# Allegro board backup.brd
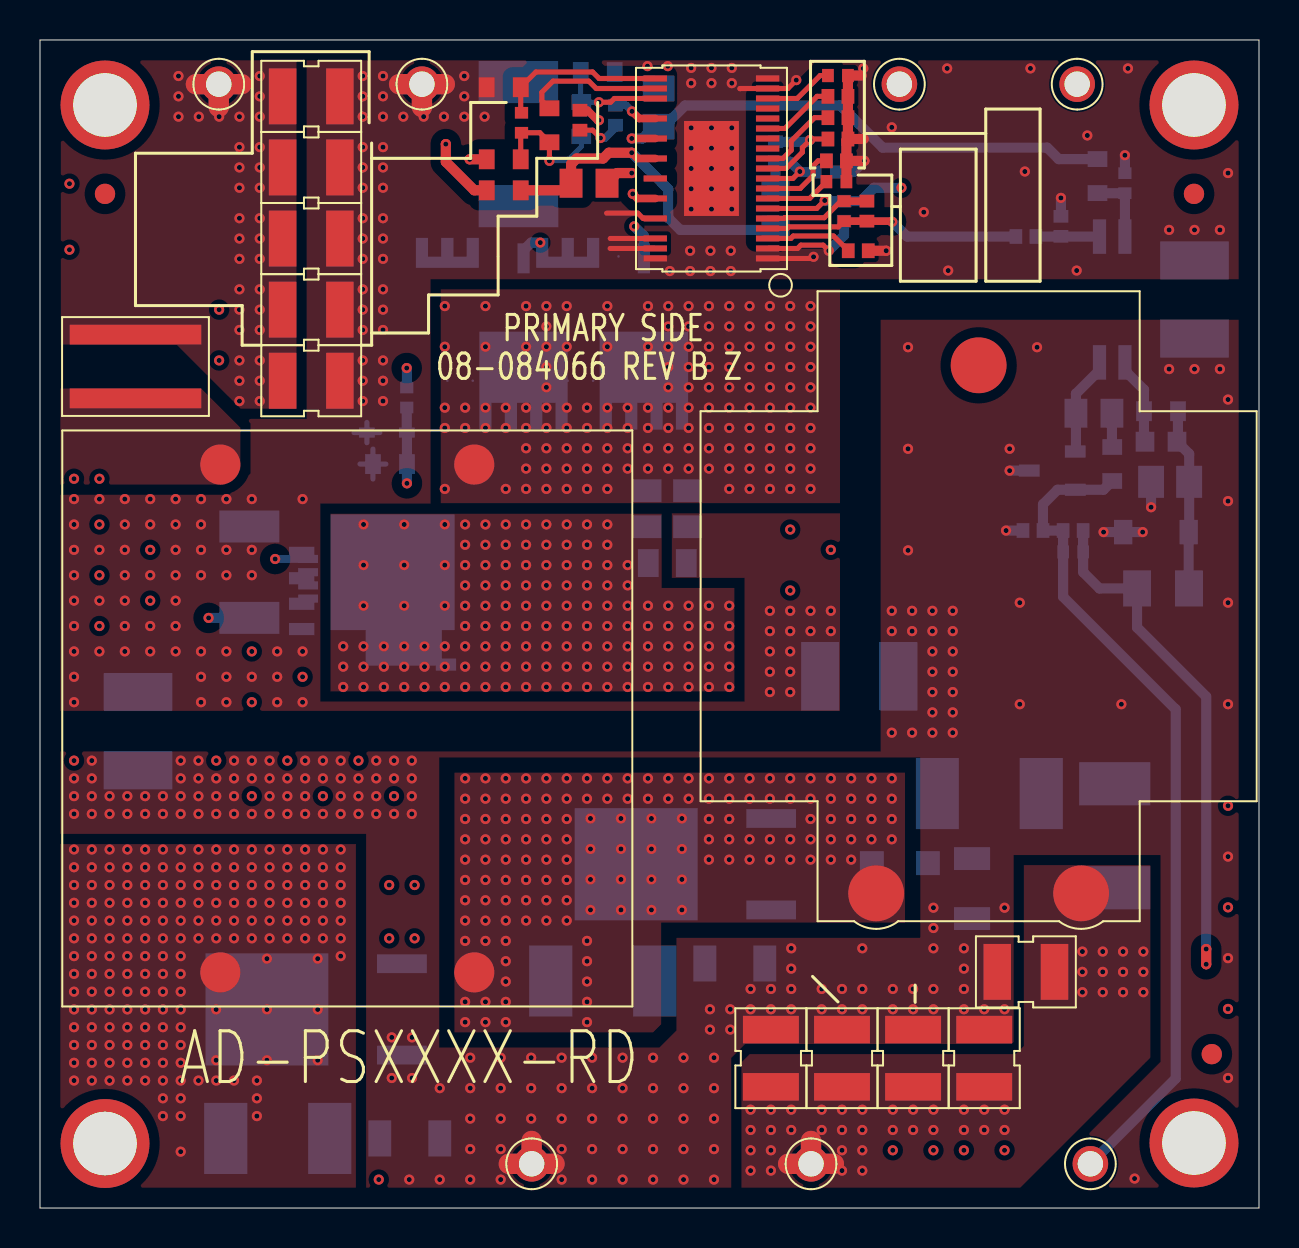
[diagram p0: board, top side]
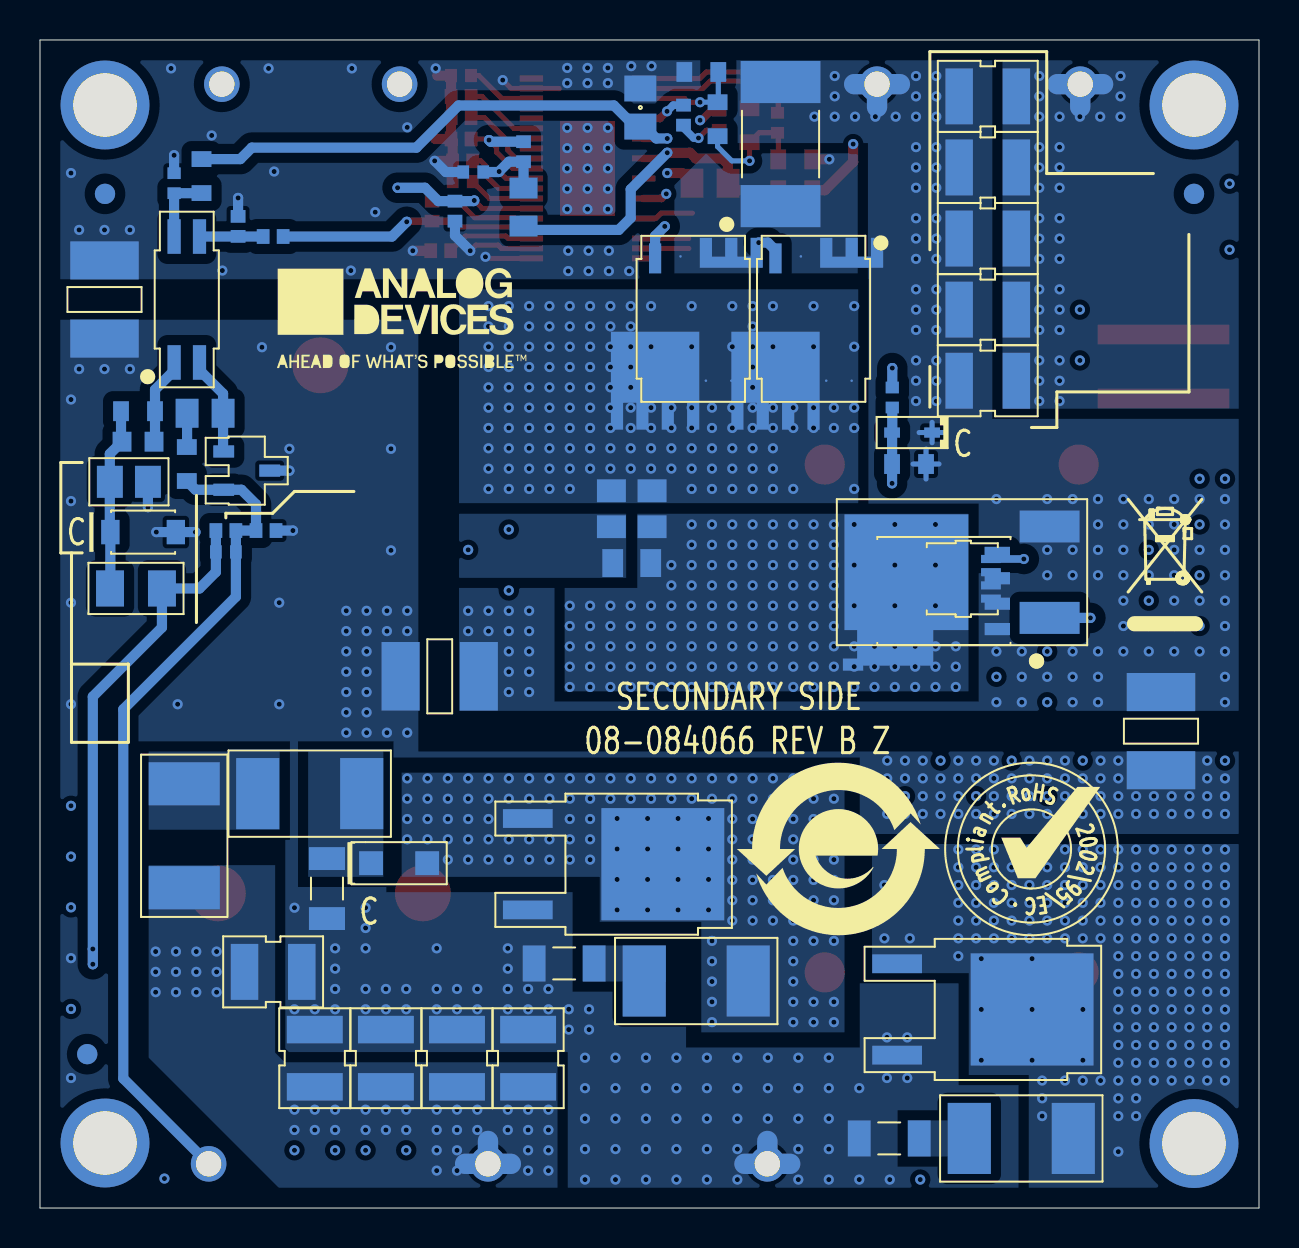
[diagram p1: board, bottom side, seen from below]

Outline 60.96 x 58.42 mm; copper layers: TOP, L2_GND, L3_SIG, L4_PWR, L5_PWR, L6_PWR, L7_GND, BOTTOM. Coordinates in mm from the lower left corner of the outline.
Outline path: 0,58.42 0,0 60.96,0 60.96,58.42 0,58.42

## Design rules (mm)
constraint set DEFAULT: min track width 0.203
net group _N100: nets _N100 _N250
net group _N372: nets _N372 N430
net group INTVCC: nets _N63 INTVCC
net group _N233: nets _N231 _N232 _N233 _N238
net group _N303: nets _N227 _N303 _N305
net group _N310: nets _N310
net group VIN: nets _N197 _N199 _N200
net group VO: nets _N54 _N55 _N59 _N61 VFB

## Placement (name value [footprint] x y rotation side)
C1  1UF  [C0805]  27.46 51.26 0 top
C2  1UF  [C0402]  39.29 51.82 180 bottom
C3  4.7UF  [C0805H60]  30.94 55.04 90 bottom
C4  1UF  [C0402]  39.83 51.33 0 top
C5  0.022uF  [C0402]  39.9 56.64 0 top
C6  470pF  [C0402]  40.21 49.86 270 top
C7  2.2UF  [C0402]  54.25 51.26 90 bottom
C8  4700pF  [C0603]  56.06 38.33 180 bottom
C9  2.2uF  [C0805H53]  56.52 36.32 180 bottom
C10  3900pF  [C0805]  52.7 39.75 0 bottom
C11  2200pF  [C0402]  24.08 54.28 90 top
C12  0.1UF  [C0402]  18.34 40.54 270 bottom
C13  1UF  [C0402]  51.66 32.82 180 bottom
C14  2200PF  [C1812H110]  40.97 26.59 0 bottom
C15  2200PF  [C1206]  46.61 15.98 270 bottom
C_D3SNUB  2200PF  [C1206]  18.49 3.48 0 bottom
C_D4SNUB  2200PF  [C1206]  34.75 12.23 0 bottom
CCLAMP  0.22UF  [C0805H55]  30.35 34.98 270 bottom
CIN1  10UF  [C1210H110]  13.56 55.6 0 top
CIN2  10UF  [C1210H110]  13.56 52.04 0 top
CIN3  10UF  [C1210H110]  13.56 48.49 0 top
CIN4  10UF  [C1210H110]  13.56 44.93 0 top
CIN5  10UF  [C1210H110]  13.56 41.38 0 top
CIN6  10UF  [C1210H110]  13.56 55.6 0 bottom
CIN7  10UF  [C1210H110]  13.56 52.04 0 bottom
CIN8  10UF  [C1210H110]  13.56 48.49 0 bottom
CIN9  10UF  [C1210H110]  13.56 44.93 0 bottom
CIN10  10UF  [C1210H110]  13.56 41.38 0 bottom
COUT1  10UF  [C1210H110]  36.55 7.49 90 top
COUT2  10UF  [C1210H110]  40.11 7.49 90 top
COUT3  10UF  [C1210H110]  43.66 7.49 90 top
COUT4  10UF  [C1210H110]  47.22 7.49 90 top
COUT5  10UF  [C1210H110]  49.3 11.81 180 top
COUT6  10UF  [C1210H110]  36.55 7.49 90 bottom
COUT7  10UF  [C1210H110]  40.11 7.49 90 bottom
COUT8  10UF  [C1210H110]  43.66 7.49 90 bottom
COUT9  10UF  [C1210H110]  47.22 7.49 90 bottom
COUT10  10UF  [C1210H110]  49.3 11.81 180 bottom
CSNUB  0.47UF  [C0805H55]  32.38 34.98 270 bottom
CY1  2200PF  [C1812H110]  4.9 23.85 270 bottom
CY2  2200PF  [C1812H110]  57.73 45.44 270 bottom
D1  BAS516,115  [SOD523F]  17.35 38.79 0 bottom
D2  CMMR1U-06 TR  [SOD123F]  43 17.25 180 bottom
D3  IDM08G120C5XTMA1  [PG-TO252-2]  12.9 9.93 270 bottom
D4  IDM08G120C5XTMA1  [PG-TO252-2]  31.37 17.2 270 bottom
D5  CMHZ4697 TR PBFREE  [SOD123FLH53]  55.8 33.81 180 bottom
L1  330UH/280UH  [LSML1075W1220H500]  46.94 30.1 0 top
NOREF  -  [unnamed]  3.25 50.72 0 top
NOREF#2  -  [#2]  0 58.42 0 top
NOREF#3  -  [#2]  105.61 60.12 0 top
NOREF#4  -  [#2]  210.86 -85.93 180 top
NOREF#5  -  [#2]  38.05 1.19 0 top
NOREF#6  -  [#2]  197.52 -89.49 0 top
NOREF#7  -  [#2]  60.96 0 90 top
NOREF#8  -  [unnamed]  57.71 3.25 0 top
NOREF#9  -  [unnamed]  3.25 55.17 0 top
NOREF#10  -  [unnamed]  57.71 50.72 0 top
NOREF#11  -  [#2]  172.74 -85.93 0 top
NOREF#12  -  [unnamed]  3.25 3.23 0 top
NOREF#13  -  [unnamed]  57.71 55.17 0 top
NOREF#14  -  [#2]  197.59 -85.93 0 top
NOREF#15  -  [#2]  214.42 -102.46 0 top
NOREF#16  -  [#2]  218.79 -87.41 0 top
NOREF#17  -  [#2]  186.04 -99.65 0 top
NOREF#18  -  [#2]  214.42 -59.45 0 top
NOREF#19  -  [#2]  -331.47 -377.44 0 top
NOREF#20  -  [#2]  60.96 0 90 top
NOREF#21  -  [#2]  31.19 73.33 0 top
NOREF#22  -  [#2]  166.3 -89.49 0 top
NOREF#23  -  [#2]  9.09 35.74 0 top
NOREF#24  -  [#2]  1.65 1.68 0 top
NOREF#25  -  [#2]  0 58.42 270 top
NOREF#26  -  [#2]  151.22 -106.76 0 top
NOREF#27  -  [#2]  60.96 58.42 180 top
NOREF#28  -  [#2]  98.15 45.06 0 top
NOREF#29  -  [#2]  208.32 -63.71 0 top
NOREF#30  -  [unnamed]  58.6 7.7 180 top
NOREF#31  -  [#2]  172.71 -45.29 0 top
NOREF#32  -  [#2]  -331.47 -377.44 0 top
NOREF#33  -  [#2]  -331.47 -377.44 0 top
NOREF#34  -  [#2]  0 0 0 top
NOREF#35  -  [unnamed]  58.6 7.7 180 bottom
NOREF#36  -  [#2]  4.9 28.91 180 bottom
NOREF#37  -  [#2]  21.03 17.96 180 bottom
NOREF#38  -  [unnamed]  57.71 50.72 180 bottom
NOREF#39  -  [unnamed]  3.25 50.72 180 bottom
NOREF#40  -  [#2]  11.38 17.96 180 bottom
NOREF#41  -  [#2]  43.16 44.48 180 bottom
Q1  IAUCN10S7N021ATMA1  [PG-TDSON-8_B]  28.3 44.48 0 bottom
Q2  IAUCN10S7N021ATMA1  [PG-TDSON-8_B]  22.28 44.48 0 bottom
Q4  DMP10H400SK3-13  [DPAK]  15.19 31.8 90 bottom
Q5  SISS71DN-T1-GE3  [POWERPAK1212-8_SP]  14.84 31.47 90 bottom
Q6  SIR873DP-T1-GE3  [POWERPAKSO8]  15.75 30.86 90 bottom
R1  0  [R0603]  23.19 50.9 0 top
R2  100K  [R0805]  36.78 50.06 90 bottom
R3  14.7K  [R0402]  36.78 52.83 270 bottom
R4  2.55K  [R0402]  39.9 53.47 180 top
R5  249K  [R0402]  39.83 52.37 180 top
R6  44.2K  [R0402]  39.9 54.53 180 top
R7  100K  [R0402]  39.9 55.6 180 top
R8  52.3K  [R0402]  41.35 49.86 270 top
R9  59K  [R0402]  49.3 48.59 0 bottom
R10  340  [R0402]  51.05 49.1 90 bottom
R11  100  [R0603]  52.88 51.61 270 bottom
R12  1.5K  [R0603]  56.06 39.85 180 bottom
R13  10K  [R1206-2]  56.16 30.99 0 bottom
R14  56.2K  [R0603]  53.62 37.21 270 bottom
R15  3.01K  [R0603]  25.48 54.15 270 top
R16  100  [R0603]  23.19 52.45 180 top
R17  100  [R0603]  23.19 56.06 180 top
R18  0  [R0603]  27.08 54.46 270 bottom
R19  0  [R0603]  27.89 56.82 0 bottom
R20  10K  [R0603]  17.5 37.21 180 bottom
R21  124K  [R2512H31]  47.47 20.73 0 bottom
R22  124K  [R2512H31]  53.75 18.62 90 bottom
R23  0  [R0402]  28.78 54.66 270 bottom
R24  10K  [R0402]  27 54.41 270 top
R_D3SNUB  124K  [R2512H31]  11.89 3.48 0 bottom
R_D4SNUB  124K  [R2512H31]  28.14 11.35 0 bottom
RC  31042-00-21-00-00-08-0  [MILLMAX3102]  42.98 56.21 0 top
RFB1  196K  [R0402]  51.66 33.88 180 bottom
RFB2  9.53K  [R0402]  49.66 33.88 180 bottom
RJUMPER  0  [R1225H28]  4.78 42.09 270 top
RSNS  0.02  [R2512H35]  23.93 53.21 90 bottom
RSNUB  200  [R0805]  31.37 32.26 180 bottom
RSYNC  2K  [R0402]  40.21 49.86 270 bottom
RT  82.5K  [R0402]  40.92 47.88 0 top
SYNC  31042-00-21-00-00-08-0  [MILLMAX3102]  51.87 56.21 0 top
T1  P26R2-0322-18R0  [TSML1102W1114H610]  15.37 24.49 180 top
TRIM  31042-00-21-00-00-08-0  [MILLMAX3102]  52.53 2.21 0 top
U1  LT3753EFE#PBF  [TSSOP38_31P_PAD4_75X2_74_05-08-1865]  33.58 51.99 90 top
U2  AN431AN-ATRG1  [SOT23_B]  50.62 36.88 270 bottom
U3  PS2801C-1-P-A  [SSOP4]  53.62 45.44 180 bottom
UNK+VIN  31042-00-21-00-00-08-0  [MILLMAX3102]  8.94 56.21 0 top
UNK+VOUT  31042-00-21-00-00-08-0  [MILLMAX3102]  38.56 2.21 0 top
UNK-VIN  31042-00-21-00-00-08-0  [MILLMAX3102]  19.1 56.21 0 top
UNK-VOUT  31042-00-21-00-00-08-0  [MILLMAX3102]  24.59 2.21 0 top

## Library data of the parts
C1 = CAP: User Part Number: UPN; Tolerance: 10; alternate symbols: (C0805); tolerance: 10
C2 C4-C7 C11-C13 = CAP: User Part Number: UPN; Tolerance: 10; alternate symbols: (C0402); tolerance: 10
C3 = CAP: Tolerance: 10; User Part Number: UPN; alternate symbols: (C0805H60); tolerance: 10
C8 = CAP: User Part Number: UPN; Tolerance: 5; alternate symbols: (C0603); tolerance: 5
C9 = CAP: Tolerance: 10; User Part Number: UPN; alternate symbols: (C0805H53); tolerance: 10
C10 = CAP: User Part Number: UPN; Tolerance: 5; alternate symbols: (C0805); tolerance: 5
C14 CY1 CY2 = CAP: Tolerance: 10; User Part Number: UPN; alternate symbols: (C1812H110); tolerance: 10
C15 C_D3SNUB C_D4SNUB = CAP: User Part Number: UPN; Tolerance: 5; alternate symbols: (C1206); tolerance: 5
CCLAMP CSNUB = CAP: User Part Number: UPN; Tolerance: 10; alternate symbols: (C0805H55); tolerance: 10
CIN1-CIN10 COUT1-COUT10 = CAP: Tolerance: 20; User Part Number: UPN; alternate symbols: (C1210H110); tolerance: 20
D1 = DIO: Tolerance: N/A; User Part Number: UPN; alternate symbols: (SOD523F); tolerance: N/A
D2 = DIO: Tolerance: N/A; User Part Number: UPN; alternate symbols: (SOD123F); tolerance: N/A
D3 D4 = DIOSCHOTTKY3P_V15: User Part Number: UPN; Tolerance: N/A; alternate symbols: (PG-TO252-2); tolerance: N/A
D5 = DIOZNR: User Part Number: UPN; Tolerance: 5; alternate symbols: (SOD123FLH53); tolerance: 5
L1 = CHOKE3P_V3: User Part Number: UPN; Tolerance: N/A; alternate symbols: (LSML1075W1220H500); tolerance: N/A
Q1 Q2 = TRANNMOSFET8P: Tolerance: N/A; User Part Number: UPN; alternate symbols: (PG-TDSON-8_B); tolerance: N/A
Q4 = TRANPMOSFET_V11: Tolerance: N/A; User Part Number: UPN; alternate symbols: (DPAK); tolerance: N/A
Q5 = TRANPMOSFET_V9: Tolerance: N/A; User Part Number: UPN; alternate symbols: (POWERPAK1212-8_SP); tolerance: N/A
Q6 = TRANPMOSFET_V9: Tolerance: N/A; User Part Number: UPN; alternate symbols: (POWERPAKSO8); tolerance: N/A
R1 R18 R19 = RES: User Part Number: UPN; Tolerance: JUMPER; alternate symbols: (R0603); tolerance: JUMPER
R2 = RES: User Part Number: UPN; Tolerance: 1; alternate symbols: (R0805); tolerance: 1
R3-R9 R24 RFB1 RFB2 RSYNC RT = RES: User Part Number: UPN; Tolerance: 1; alternate symbols: (R0402); tolerance: 1
R10 = RES: User Part Number: UPN; Tolerance: 0.1; alternate symbols: (R0402); tolerance: 0.1
R11 R14-R17 R20 = RES: User Part Number: UPN; Tolerance: 1; alternate symbols: (R0603); tolerance: 1
R12 = RES: User Part Number: UPN; Tolerance: 5; alternate symbols: (R0603); tolerance: 5
R13 = RES: Tolerance: 5; User Part Number: UPN; alternate symbols: (R1206-2); tolerance: 5
R21 R22 R_D3SNUB R_D4SNUB = RES: User Part Number: UPN; Tolerance: 1; alternate symbols: (R2512H31); tolerance: 1
R23 = RES: User Part Number: UPN; Tolerance: JUMPER; alternate symbols: (R0402); tolerance: JUMPER
RC SYNC TRIM UNK+VIN UNK+VOUT UNK-VIN UNK-VOUT = CNTP1P: User Part Number: UPN; Tolerance: N/A; alternate symbols: (MILLMAX3102); tolerance: N/A
RJUMPER = RES: User Part Number: UPN; Tolerance: N/A; alternate symbols: (R1225H28); tolerance: N/A
RSNS = RES: User Part Number: UPN; Tolerance: 1; alternate symbols: (R2512H35); tolerance: 1
RSNUB = RES: User Part Number: UPN; Tolerance: 5; alternate symbols: (R0805); tolerance: 5
T1 = XFMR_4P_V7: User Part Number: UPN; Tolerance: N/A; alternate symbols: (TSML1102W1114H610); tolerance: N/A
U1 = ADLT3753: Tolerance: N/A; User Part Number: UPN; alternate symbols: (TSSOP38_31P_PAD4_75X2_74_05-08-1865); tolerance: N/A
U2 = ICAN431: User Part Number: UPN; Tolerance: N/A; alternate symbols: (SOT23_B); tolerance: N/A
U3 = TRANPS2801_1: User Part Number: UPN; Tolerance: N/A; alternate symbols: (SSOP4); tolerance: N/A

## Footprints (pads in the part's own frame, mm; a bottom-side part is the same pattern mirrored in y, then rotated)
C0402
  rect 0.584x0.66 smd: 1(-0.5,0) 2(0.5,0)
C0603
  rect 0.94x0.991 smd: 1(-0.8,0) 2(0.8,0)
C0805
  rect 1.143x1.448 smd: 1(-0.9,0) 2(0.9,0)
C0805H53
  rect 1.295x1.6 smd: 1(-0.953,0) 2(0.953,0)
C0805H55
  rect 1.143x1.448 smd: 1(-0.9,0) 2(0.9,0)
C0805H60
  rect 1.295x1.6 smd: 1(-0.953,0) 2(0.953,0)
C1206
  rect 1.143x1.803 smd: 1(-1.5,0) 2(1.5,0)
C1210H110
  rect 1.372x2.794 smd: 1(-1.431,0) 2(1.431,0)
C1812H110
  rect 1.905x3.429 smd: 1(-1.956,0) 2(1.956,0)
DPAK
  rect 1.6x2.997 smd: 1(-2.286,-4.718) 3(2.286,-4.718)
  rect 5.791x6.198 smd: 4(0,2.445)
LSML1075W1220H500
  round 2.794 smd: 1(-5.125,-14.36) 2(5.125,-14.36) 3(0,12.05)
MILLMAX3102
  round 1.778 hole 1.27: 1(0,0)
PG-TDSON-8_B
  custom 0.375x0.375 smd: 1(-1.905,-3.3)
  round 0.127 smd: 2(-0.635,-3.12) 3(0.635,-3.12) 6(0.635,3.097) 7(-0.635,3.097) 8(-1.905,3.097)
  rect 0.61x1.499 smd: 4(1.905,-3.021)
  custom 1.105x1.105 smd: 5(1.905,3.097)
PG-TO252-2
  rect 0.94x2.489 smd: 1(-2.285,-5.195) 2(2.285,-5.195)
  rect 5.613x6.147 smd: 3(0,1.555)
POWERPAK1212-8_SP
  rect 0.406x0.991 smd: 1(-0.991,-1.435) 2(-0.33,-1.435) 3(0.33,-1.435) 4(0.991,-1.435)
  round 0.127 smd: 5(0.991,1.676) 6(0.33,1.676) 7(-0.33,1.676)
  custom 0.559x0.559 smd: 8(-0.991,1.676)
POWERPAKSO8
  rect 0.61x1.27 smd: 1(-1.905,-2.667) 2(-0.635,-2.667) 3(0.635,-2.667) 4(1.905,-2.667)
  rect 0.61x1.016 smd: 5(1.905,2.794) 6(0.635,2.794) 7(-0.635,2.794)
  custom 1.041x1.041 smd: 8(-1.905,2.794)
R0402
  rect 0.635x0.737 smd: 1(-0.5,0) 2(0.5,0)
R0603
  rect 0.787x0.991 smd: 1(-0.85,0) 2(0.85,0)
R0805
  rect 1.041x1.397 smd: 1(-0.95,0) 2(0.95,0)
R1206-2
  rect 1.397x1.803 smd: 1(-1.298,0) 2(1.298,0)
R1225H28
  rect 0.991x6.579 smd: 1(-1.595,0) 2(1.595,0)
R2512H31
  rect 2.159x3.556 smd: 1(-2.6,0) 2(2.6,0)
R2512H35
  rect 2.108x3.988 smd: 1(-3.104,0) 2(3.104,0)
SOD123F
  rect 1.194x1.194 smd: A(1.403,0) C(-1.403,0)
SOD123FLH53
  rect 0.914x1.219 smd: A(1.638,0) C(-1.638,0)
SOD523F
  rect 0.787x0.508 smd: A(1,0) C(-1,0)
SOT23_B
  rect 0.61x1.041 smd: 1(-0.958,-1.15) 2(0.958,-1.15) 3(0,1.15)
SSOP4
  rect 0.66x1.727 smd: 1(-0.635,-3.149) 2(0.635,-3.149) 3(0.635,3.149) 4(-0.635,3.149)
TSML1102W1114H610
  round 2.007 smd: 2(-6.35,-12.7) 6(6.35,-12.7) 9(6.35,12.7) 13(-6.35,12.7)
TSSOP38_31P_PAD4_75X2_74_05-08-1865
  rect 0.305x1.168 smd: 1(-4.5,-2.809) 2(-4,-2.809) 3(-3.5,-2.809) 4(-3,-2.809) 5(-2.5,-2.809) 6(-2,-2.809) 7(-1.5,-2.809) 8(-1,-2.809) 9(-0.5,-2.809) 10(0,-2.809) 11(0.5,-2.809) 12(1,-2.809) 13(1.5,-2.809) 14(2,-2.809) 15(2.5,-2.809) 16(3,-2.809) 17(3.5,-2.809) 18(4,-2.809) 19(4.5,-2.809) 20(4.5,2.809) 21(4,2.809) 22(3.5,2.809) 24(2.5,2.809) 26(1.5,2.809) 28(0.5,2.809) 30(-0.5,2.809) 32(-1.5,2.809) 34(-2.5,2.809) 36(-3.5,2.809) 37(-4,2.809) 38(-4.5,2.809)
  rect 4.75x2.743 smd: 39(0,0)
unnamed
  round 1.016 smd: (0,0)

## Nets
AGND: C1.2(N2) C2.1 C3.2(N2) C4.2(N2) C5.2(N2) C7.2(N2) C14.1 CIN1.2(N2) CIN2.2(N2) CIN3.2(N2) CIN4.2(N2) CIN5.2(N2) CIN6.2(N2) CIN7.2(N2) CIN8.2(N2) CIN9.2(N2) CIN10.2(N2) CY1.1 CY2.1 D1.C Q4.3(S) Q5.1 Q5.2 Q5.3(S3) Q6.1 Q6.2 Q6.3(S3) R4.1 R5.1 R6.1 R7.1 R10.2(N2) R17.2(N2) R19.2(N2) R20.2(N2) R24.1 RSNS.2(N2) RSYNC.2(N2) RT.2(N2) U1.1 U1.2 U1.18 U1.19 U1.34 U1.36 U1.37 U1.38 U1.39 UNK-VIN.1
GND_ISO: C9.2(N2) C14.2(N2) C15.2(N2) C_D3SNUB.2(N2) C_D4SNUB.2(N2) COUT1.2(N2) COUT2.2(N2) COUT3.2(N2) COUT4.2(N2) COUT5.2(N2) COUT6.2(N2) COUT7.2(N2) COUT8.2(N2) COUT9.2(N2) COUT10.2(N2) CY1.2(N2) CY2.2(N2) D3.2 D4.2 D5.A(P) RFB2.2(N2) U2.3 UNK-VOUT.1
VIN: CIN1.1 CIN2.1 CIN3.1 CIN4.1 CIN5.1 CIN6.1 CIN7.1 CIN8.1 CIN9.1 CIN10.1 R1.1 RJUMPER.1 UNK+VIN.1
VIN_X: RJUMPER.2(N2) T1.6
_N37: D3.1 D3.3(CASE) R_D3SNUB.1 T1.9
_N54: C10.2(N2) R14.1
_N55: C10.1 U2.1 U3.2
_N59: C8.1 C9.1 D5.C R12.1 R13.2(N2)
_N61: C8.2(N2) R12.2(N2) U3.1
_N63: C7.1 R11.2(N2) U3.4
_N100: C12.1 U1.32
_N197: C1.1 R1.2(N2) R2.1 U1.28(VIN)
_N199: R3.1 R4.2(N2) U1.10
_N200: C2.2(N2) R2.2(N2) R3.2(N2) RC.1(N1) U1.9
_N202: R5.2(N2) U1.8
_N203: R6.2(N2) U1.11
_N204: R7.2(N2) U1.14
_N213: RT.1 U1.3
_N216: C4.1 U1.7
_N217: C5.1 U1.17
_N227: C6.1 R8.1 U1.5
_N231: R18.1 R19.1 U1.22
_N232: C11.1 R15.2(N2) R16.1 R18.2(N2)
_N233: R15.1 U1.21
_N238: C11.2(N2) R17.1 U1.20
_N250: C12.2(N2) D1.A(P) Q4.1 Q5.4 Q6.4 R20.1
_N264: R21.2(N2) R22.2(N2)
_N265: C15.1 D2.C R21.1
_N274: D2.A(P) D4.1 D4.3(CASE) L1.1 R_D4SNUB.1 T1.13(N4)
_N303: C6.2(N2) R8.2(N2) R9.1 U1.4
_N305: R9.2(N2) R10.1 U3.3(EMITTER)
_N310: CSNUB.2(N2) RSNUB.1
_N365: CCLAMP.2(N2) Q4.4 Q5.5 Q5.6 Q5.7 Q5.8 Q6.5 Q6.6 Q6.7 Q6.8 RSNUB.2(N2)
_N372: R23.1 U1.24
_N375: C_D4SNUB.1 R_D4SNUB.2(N2)
_N387: C_D3SNUB.1 R_D3SNUB.2(N2)
INTVCC: C3.1 R11.1 U1.26
N396: CCLAMP.1 CSNUB.1 Q1.5 Q1.6 Q1.7 Q1.8 Q2.5 Q2.6 Q2.7 Q2.8 T1.2
N430: Q1.4 Q2.4 R23.2(N2) R24.2(N2)
N436: Q1.1 Q1.2 Q1.3(S3) Q2.1 Q2.2 Q2.3(S3) R16.2(N2) RSNS.1
SYNC: RSYNC.1 SYNC.1(N1) U1.6
VFB: C13.2(N2) R14.2(N2) RFB1.2(N2) RFB2.1 TRIM.1(N1) U2.2(REF)
VO: C13.1 COUT1.1 COUT2.1 COUT3.1 COUT4.1 COUT5.1 COUT6.1 COUT7.1 COUT8.1 COUT9.1 COUT10.1 L1.2 R13.1 R22.1 RFB1.1 UNK+VOUT.1

Pads without a net: L1 3; U1 12 13 15 16 30

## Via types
v1: diameter 0.508, hole 0.254, TOP to BOTTOM, 1065 vias

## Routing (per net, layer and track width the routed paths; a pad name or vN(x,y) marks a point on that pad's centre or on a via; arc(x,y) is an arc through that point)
AGND: length 66.7
  TOP w0.254: U1.34 30.16,49.49 29.9,49.76 28.34,49.76 ; v1(38.68,47.57) 38.6,47.49 U1.1 ; v1(39.45,47.88) 39.17,48.16 38.05,48.16 37.88,47.99 U1.2 ; U1.36 28.52,48.49 ; v1(37.82,56.41) 37.4,55.99 U1.18 35.01,55.99 35,55.98 ; U1.37 28.51,47.99
  TOP w0.381: R24.1 27.38,54.91 27.88,54.41 v1(27.95,54.41)
  TOP w0.508: C1.2 28.87,51.77 v1(29.59,51.77) ; 41.1,56.64 C5.2 R7.1 R6.1 R4.1 ; R4.1 41.2,53.47 ; R4.1 40.33,53.39 R5.1 ; R5.1 C4.2 ; R5.1 v1(41.22,52.37) ; RT.2 v1(42.32,47.88)
  TOP w1.016: 17.96,56.21 UNK-VIN.1 ; UNK-VIN.1 19.1,55.07 ; UNK-VIN.1 20.24,56.21
  L2_GND w1.016: 19.1,55.07 UNK-VIN.1 ; UNK-VIN.1 20.24,56.21 ; UNK-VIN.1 17.96,56.21
  L3_SIG w0.203: v1(16.14,53.06) v1(16.14,52.04) ; v1(17.15,53.06) v1(17.15,52.04)
  L3_SIG w1.016: 19.1,55.07 UNK-VIN.1 ; UNK-VIN.1 17.96,56.21 ; UNK-VIN.1 20.24,56.21
  L4_PWR w1.016: UNK-VIN.1 20.24,56.21 ; UNK-VIN.1 17.96,56.21 ; UNK-VIN.1 19.1,55.07
  L5_PWR w1.016: UNK-VIN.1 20.24,56.21 ; UNK-VIN.1 19.1,55.07 ; UNK-VIN.1 17.96,56.21
  L6_PWR w1.016: UNK-VIN.1 20.24,56.21 ; UNK-VIN.1 17.96,56.21 ; UNK-VIN.1 19.1,55.07
  L7_GND w1.016: UNK-VIN.1 20.24,56.21 ; UNK-VIN.1 19.1,55.07 ; UNK-VIN.1 17.96,56.21
  BOTTOM w0.254: D1.C 17,38.79 ; D1.C 16.35,38.28 ; D1.C 16.35,39.29 ; D1.C 15.7,38.79 ; 16.65,36.46 R20.2 ; R20.2 16.65,37.96 ; R20.2 17.3,37.21 ; R20.2 16,37.21
  BOTTOM w0.508: v1(39.45,47.88) 40.21,48.64 RSYNC.2 ; v1(41.22,52.37) 40.67,51.82 C2.1 ; R10.2 v1(51.05,50.52) ; C7.2 v1(54.25,52.65)
  BOTTOM w1.016: UNK-VIN.1 20.24,56.21 ; UNK-VIN.1 19.1,55.07 ; UNK-VIN.1 17.96,56.21
  vias: v1(1.47,51.23) v1(1.47,47.93) v1(1.7,35.46) v1(1.7,34.19) v1(1.7,32.92) v1(1.7,31.65) v1(1.7,30.38) v1(1.7,29.11) v1(1.7,27.84) v1(1.7,26.57) v1(1.7,25.3) v1(2.97,35.46) v1(2.97,32.92) v1(2.97,30.38) v1(2.97,27.84) v1(4.24,35.46) v1(4.24,34.19) v1(4.24,32.92) v1(4.24,31.65) v1(4.24,30.38) v1(4.24,29.11) v1(4.24,27.84) v1(5.51,35.46) v1(5.51,34.19) v1(5.51,31.65) v1(5.51,29.11) v1(5.51,27.84) v1(6.78,35.46) v1(6.78,34.19) v1(6.78,32.92) v1(6.78,31.65) v1(6.78,30.38) v1(6.78,29.11) v1(6.78,27.84) v1(8.05,35.46) v1(8.05,34.19) v1(8.05,32.92) v1(8.05,31.65) v1(8.05,27.84) v1(8.05,26.57) v1(8.05,25.3) v1(9.32,35.46) v1(9.32,32.92) v1(9.32,31.65) v1(9.32,27.84) v1(9.32,26.57) v1(9.32,25.3) v1(10.59,35.46) v1(10.59,32.92) v1(10.59,31.65) v1(10.59,26.57) v1(11.86,27.84) v1(11.86,26.57) v1(11.86,25.3) v1(13.13,35.46) v1(13.13,27.84) v1(13.13,25.3) v1(16.14,56.62) v1(16.14,55.6) v1(16.14,54.58) v1(16.14,51.03) v1(16.14,49.5) v1(16.14,48.49) v1(16.14,47.47) v1(16.14,45.95) v1(16.14,44.93) v1(16.14,43.92) v1(16.14,42.39) v1(16.14,41.38) v1(16.14,40.36) v1(17.15,56.62) v1(17.15,55.6) v1(17.15,54.58) v1(17.15,51.03) v1(17.15,49.5) v1(17.15,48.49) v1(17.15,47.47) v1(17.15,45.95) v1(17.15,44.93) v1(17.15,43.92) v1(17.15,42.39) v1(17.15,41.38) v1(17.15,40.36) v1(18.17,54.58) v1(19.19,54.58) v1(20.2,54.58) v1(21.22,56.62) v1(21.22,55.6) v1(21.22,54.58) v1(22.23,54.58) v1(30.38,57.11) v1(31.39,57.11) v1(31.5,46.86) v1(32.56,57.02) v1(32.56,56.26) v1(32.56,54.03) v1(32.56,53.01) v1(32.56,51.99) v1(32.56,50.98) v1(32.56,49.96) v1(32.51,47.88) v1(32.51,46.86) v1(33.58,57.02) v1(33.58,56.26) v1(33.58,54.03) v1(33.58,53.01) v1(33.58,51.99) v1(33.58,50.98) v1(33.58,49.96) v1(33.53,47.88) v1(33.53,46.86) v1(34.59,57.02) v1(34.59,56.26) v1(34.59,54.03) v1(34.59,53.01) v1(34.59,51.99) v1(34.59,50.98) v1(34.59,49.96) v1(34.54,47.88) v1(34.54,46.86) v1(36.5,29.87) v1(36.5,28.85) v1(36.5,27.84) v1(36.5,26.82) v1(36.5,25.81) v1(37.52,29.87) v1(37.52,28.85) v1(37.52,27.84) v1(37.52,26.82) v1(37.52,25.81) v1(38.53,29.87) v1(38.53,28.85) v1(39.55,29.87) v1(39.55,28.85) v1(41.17,57) v1(42.6,54.05) v1(44.2,49.81) v1(45.36,57) v1(45.42,46.89) v1(49.25,51.84) v1(49.53,57) v1(51.84,46.89) v1(52.37,53.64) v1(54.41,57) v1(56.46,48.92) v1(57.73,48.92) v1(59,48.92) v1(59.41,51.77)
GND_ISO: length 25.6
  TOP w1.016: 23.44,2.21 UNK-VOUT.1 ; UNK-VOUT.1 25.73,2.21 ; UNK-VOUT.1 24.59,3.35
  L2_GND w1.016: 23.44,2.21 UNK-VOUT.1 ; UNK-VOUT.1 24.59,3.35 ; UNK-VOUT.1 25.73,2.21
  L3_SIG w1.016: UNK-VOUT.1 25.73,2.21 ; UNK-VOUT.1 23.44,2.21 ; UNK-VOUT.1 24.59,3.35
  L6_PWR w1.016: UNK-VOUT.1 25.73,2.21 ; UNK-VOUT.1 23.44,2.21 ; UNK-VOUT.1 24.59,3.35
  L7_GND w1.016: UNK-VOUT.1 25.73,2.21 ; UNK-VOUT.1 23.44,2.21 ; UNK-VOUT.1 24.59,3.35
  BOTTOM w0.508: v1(55.14,33.81) D5.A v1(53.19,33.81) ; RFB2.2 v1(48.31,33.88) ; C9.2 v1(55.56,35.05) ; U2.3 v1(48.49,36.88)
  BOTTOM w1.016: 23.44,2.21 UNK-VOUT.1 ; UNK-VOUT.1 24.59,3.35 ; UNK-VOUT.1 25.73,2.21
  vias: v1(1.7,21.49) v1(1.7,20.6) v1(1.7,19.71) v1(2.59,22.38) v1(2.59,21.49) v1(2.59,20.6) v1(2.59,19.71) v1(3.48,20.6) v1(3.48,19.71) v1(4.37,20.6) v1(4.37,19.71) v1(5.26,20.6) v1(5.26,19.71) v1(6.15,20.6) v1(6.15,19.71) v1(7.04,22.38) v1(7.04,21.49) v1(7.04,20.6) v1(7.04,19.71) v1(7.92,22.38) v1(7.92,21.49) v1(7.92,20.6) v1(7.92,19.71) v1(8.81,21.49) v1(8.81,20.6) v1(8.81,19.71) v1(9.7,22.38) v1(9.7,21.49) v1(9.7,20.6) v1(9.7,19.71) v1(10.59,22.38) v1(10.59,21.49) v1(10.59,19.71) v1(11.48,22.38) v1(11.48,21.49) v1(11.48,20.6) v1(11.48,19.71) v1(12.37,21.49) v1(12.37,20.6) v1(12.37,19.71) v1(13.26,22.38) v1(13.26,21.49) v1(13.26,20.6) v1(13.26,19.71) v1(14.15,22.38) v1(14.15,21.49) v1(14.15,19.71) v1(15.04,22.38) v1(15.04,21.49) v1(15.04,20.6) v1(15.04,19.71) v1(15.93,21.49) v1(15.93,20.6) v1(15.93,19.71) v1(16.81,22.38) v1(16.81,21.49) v1(16.81,20.6) v1(16.81,19.71) v1(17.59,8.53) v1(17.59,6.5) v1(17.7,22.38) v1(17.7,21.49) v1(17.7,19.71) v1(18.47,1.42) v1(18.59,22.38) v1(18.59,21.49) v1(18.59,20.6) v1(18.59,19.71) v1(18.61,8.53) v1(18.61,6.5) v1(19.99,5.99) v1(19.99,1.42) v1(21.51,7.52) v1(21.51,5.99) v1(21.51,4.47) v1(21.51,2.95) v1(21.51,1.42) v1(23.04,7.52) v1(23.04,5.99) v1(23.04,4.47) v1(23.04,2.95) v1(23.04,1.42) v1(24.56,7.52) v1(24.56,5.99) v1(24.56,4.47) v1(26.09,7.52) v1(26.09,5.99) v1(26.09,4.47) v1(26.09,2.95) v1(26.09,1.42) v1(27.61,7.52) v1(27.61,5.99) v1(27.61,4.47) v1(27.61,2.95) v1(27.61,1.42) v1(29.13,7.52) v1(29.13,5.99) v1(29.13,4.47) v1(29.13,2.95) v1(29.13,1.42) v1(30.66,7.52) v1(30.66,5.99) v1(30.66,4.47) v1(30.66,2.95) v1(30.66,1.42) v1(32.18,7.52) v1(32.18,5.99) v1(32.18,4.47) v1(32.18,2.95) v1(32.18,1.42) v1(33.5,9.94) v1(33.5,8.92) v1(33.71,7.52) v1(33.71,5.99) v1(33.71,4.47) v1(33.71,2.95) v1(33.71,1.42) v1(34.52,9.94) v1(34.52,8.92) v1(35.53,10.96) v1(35.53,9.94) v1(36.55,10.96) v1(36.55,9.94) v1(37.57,12.99) v1(37.57,11.97) v1(37.57,10.96) v1(37.57,9.94) v1(39.09,10.96) v1(39.09,9.94) v1(40.11,10.96) v1(40.11,9.94) v1(41.12,12.99) v1(41.12,10.96) v1(41.12,9.94) v1(42.6,29.87) v1(42.6,28.85) v1(42.6,23.77) v1(42.65,10.96) v1(42.65,9.94) v1(43.41,43.05) v1(43.41,37.97) v1(43.41,32.89) v1(43.61,29.87) v1(43.61,28.85) v1(43.61,23.77) v1(43.66,10.96) v1(43.66,9.94) v1(44.63,29.87) v1(44.63,28.85) v1(44.63,27.84) v1(44.63,26.82) v1(44.63,25.81) v1(44.63,24.79) v1(44.63,23.77) v1(44.68,15.02) v1(44.68,14) v1(44.68,12.99) v1(44.68,10.96) v1(44.68,9.94) v1(45.64,29.87) v1(45.64,28.85) v1(45.64,27.84) v1(45.64,26.82) v1(45.64,25.81) v1(45.64,24.79) v1(45.64,23.77) v1(46.2,12.99) v1(46.2,11.97) v1(46.2,10.96) v1(46.2,9.94) v1(47.22,9.94) v1(48.23,15.02) v1(48.23,9.94) v1(48.49,37.97) v1(49,30.28) v1(49,25.2) v1(49.86,43.05) v1(54.08,25.2) v1(54.74,1.47) v1(56.46,41.96) v1(57.73,41.96) v1(59,41.96) v1(59.41,40.44) v1(59.41,35.36) v1(59.41,30.28) v1(59.41,25.2) v1(59.41,17.58) v1(59.41,12.5) v1(59.41,6.5)
VIN: length 23.9
  TOP w0.508: R1.1 21.72,50.9 20.29,52.32 v1(20.29,53.21)
  TOP w1.016: 8.94,55.07 UNK+VIN.1 ; UNK+VIN.1 7.8,56.21 ; UNK+VIN.1 10.08,56.21
  L3_SIG w0.508: v1(20.29,53.21) 19.74,53.77 12.34,53.77 11.38,54.74 10.79,54.74
  L3_SIG w1.016: 8.94,55.07 UNK+VIN.1 ; UNK+VIN.1 10.08,56.21 ; UNK+VIN.1 7.8,56.21
  BOTTOM w1.016: UNK+VIN.1 10.08,56.21 ; UNK+VIN.1 7.8,56.21 ; UNK+VIN.1 8.94,55.07
  vias: v1(6.93,56.62) v1(6.93,55.6) v1(6.93,54.58) v1(7.94,54.58) v1(8.96,54.58) v1(9.97,54.58) v1(9.97,53.06) v1(9.97,52.04) v1(9.97,51.03) v1(9.97,49.5) v1(9.97,48.49) v1(9.97,47.47) v1(9.97,45.95) v1(9.97,44.93) v1(9.97,43.92) v1(9.97,42.39) v1(9.97,41.38) v1(9.97,40.36) v1(10.99,56.62) v1(10.99,55.6) v1(10.99,54.58) v1(10.99,53.06) v1(10.99,52.04) v1(10.99,51.03) v1(10.99,49.5) v1(10.99,48.49) v1(10.99,47.47) v1(10.99,45.95) v1(10.99,44.93) v1(10.99,43.92) v1(10.99,42.39) v1(10.99,41.38) v1(10.99,40.36)
_N37:
  vias: v1(1.7,22.38) v1(1.7,17.93) v1(1.7,17.04) v1(1.7,16.15) v1(1.7,15.27) v1(1.7,14.38) v1(1.7,13.49) v1(1.7,12.6) v1(1.7,11.71) v1(1.7,10.82) v1(1.7,9.93) v1(1.7,9.04) v1(1.7,8.15) v1(1.7,7.26) v1(1.7,6.38) v1(2.59,17.93) v1(2.59,17.04) v1(2.59,16.15) v1(2.59,15.27) v1(2.59,14.38) v1(2.59,13.49) v1(2.59,12.6) v1(2.59,11.71) v1(2.59,10.82) v1(2.59,9.93) v1(2.59,9.04) v1(2.59,8.15) v1(2.59,7.26) v1(2.59,6.38) v1(3.48,17.93) v1(3.48,17.04) v1(3.48,16.15) v1(3.48,15.27) v1(3.48,14.38) v1(3.48,13.49) v1(3.48,12.6) v1(3.48,11.71) v1(3.48,10.82) v1(3.48,9.93) v1(3.48,9.04) v1(3.48,8.15) v1(3.48,7.26) v1(3.48,6.38) v1(4.37,17.93) v1(4.37,17.04) v1(4.37,16.15) v1(4.37,15.27) v1(4.37,14.38) v1(4.37,13.49) v1(4.37,12.6) v1(4.37,11.71) v1(4.37,10.82) v1(4.37,9.93) v1(4.37,9.04) v1(4.37,8.15) v1(4.37,7.26) v1(4.37,6.38) v1(5.26,17.93) v1(5.26,17.04) v1(5.26,16.15) v1(5.26,15.27) v1(5.26,14.38) v1(5.26,13.49) v1(5.26,12.6) v1(5.26,11.71) v1(5.26,10.82) v1(5.26,9.93) v1(5.26,9.04) v1(5.26,8.15) v1(5.26,7.26) v1(5.26,6.38) v1(6.15,17.93) v1(6.15,17.04) v1(6.15,16.15) v1(6.15,15.27) v1(6.15,14.38) v1(6.15,13.49) v1(6.15,12.6) v1(6.15,11.71) v1(6.15,10.82) v1(6.15,9.93) v1(6.15,9.04) v1(6.15,8.15) v1(6.15,7.26) v1(6.15,6.38) v1(6.15,5.49) v1(6.15,4.6) v1(7.04,17.93) v1(7.04,17.04) v1(7.04,16.15) v1(7.04,15.27) v1(7.04,14.38) v1(7.04,13.49) v1(7.04,12.6) v1(7.04,11.71) v1(7.04,10.82) v1(7.04,9.93) v1(7.04,9.04) v1(7.04,8.15) v1(7.04,7.26) v1(7.04,6.38) v1(7.04,5.49) v1(7.04,4.6) v1(7.04,2.82) v1(7.92,17.93) v1(7.92,17.04) v1(7.92,16.15) v1(7.92,15.27) v1(7.92,14.38) v1(7.92,13.49) v1(7.92,6.38) v1(8.81,22.38) v1(8.81,17.93) v1(8.81,17.04) v1(8.81,16.15) v1(8.81,15.27) v1(8.81,14.38) v1(8.81,13.49) v1(8.81,9.93) v1(8.81,7.39) v1(8.81,6.38) v1(9.7,17.93) v1(9.7,17.04) v1(9.7,16.15) v1(9.7,15.27) v1(9.7,14.38) v1(9.7,13.49) v1(9.7,6.38) v1(10.59,20.6) v1(10.59,17.93) v1(10.59,17.04) v1(10.59,16.15) v1(10.59,15.27) v1(10.59,14.38) v1(10.59,13.49) v1(10.85,6.38) v1(10.85,5.49) v1(10.85,4.6) v1(11.35,12.47) v1(11.35,9.93) v1(11.35,7.39) v1(11.48,17.93) v1(11.48,17.04) v1(11.48,16.15) v1(11.48,15.27) v1(11.48,14.38) v1(11.48,13.49) v1(12.37,22.38) v1(12.37,17.93) v1(12.37,17.04) v1(12.37,16.15) v1(12.37,15.27) v1(12.37,14.38) v1(12.37,13.49) v1(13.26,17.93) v1(13.26,17.04) v1(13.26,16.15) v1(13.26,15.27) v1(13.26,14.38) v1(13.26,13.49) v1(13.89,12.47) v1(13.89,9.93) v1(13.89,7.39) v1(14.15,20.6) v1(14.15,17.93) v1(14.15,17.04) v1(14.15,16.15) v1(14.15,15.27) v1(14.15,14.38) v1(14.15,13.49) v1(15.04,17.93) v1(15.04,17.04) v1(15.04,16.15) v1(15.04,15.27) v1(15.04,14.38) v1(15.04,13.49) v1(15.04,12.6) v1(15.93,22.38) v1(16.94,1.42) v1(17.46,16.15) v1(17.46,13.49) v1(17.7,20.6) v1(18.73,16.15) v1(18.73,13.49)
_N54: length 1.7
  BOTTOM w0.508: R14.1 53.6,38.08 C10.2
_N55: length 5
  BOTTOM w0.508: U2.1 51.81,37.87 C10.1 51.81,40.73 52.98,41.91 U3.2
_N59: length 9.2
  BOTTOM w0.508: R13.2 57.44,31 D5.C 57.47,33.83 C9.1 57.47,37.72 C8.1 56.91,38.38 R12.1
_N61: length 4.4
  BOTTOM w0.508: U3.1 54.25,41.88 55.21,40.93 R12.2 55.21,38.38 C8.2
_N63: length 3.5
  BOTTOM w0.508: R11.2 52.89,50.76 C7.1 U3.4
_N100: length 20.3
  TOP w0.381: U1.32 29.87,50.49 v1(29.64,50.72)
  L3_SIG w0.508: v1(29.64,50.72) 21.56,50.72 18.34,47.5 v1(18.34,42.01)
  BOTTOM w0.508: C12.1 v1(18.34,42.01)
_N197: length 17.9
  TOP w0.381: v1(29.59,52.78) 29.88,52.49 U1.28
  TOP w0.508: v1(29.59,52.78) 28.45,52.78 28.16,52.49 26.84,52.49 26.56,52.21 C1.1 26.2,50.9 R1.2
  BOTTOM w0.508: R2.1 36.59,48.92 32.02,48.92 31.42,49.52 31.42,50.95 v1(29.59,52.78)
_N199: length 5.5
  TOP w0.254: R4.2 38.56,53.47 v1(38.51,53.42) 38.13,53.04 38.13,52.81 37.31,51.99 U1.10
  BOTTOM w0.508: v1(38.51,53.42) 38.42,53.33 R3.1
_N200: length 12.1
  TOP w0.254: U1.9 37.65,51.49 v1(38,51.84)
  L3_SIG w0.508: RC.1 41.17,54.41 40.56,54.41 v1(38,51.84)
  BOTTOM w0.508: R2.2 R3.2 37.51,52.33 v1(38,51.84) 38.02,51.82 C2.2
_N202: length 3.8
  TOP w0.254: U1.8 38.01,50.99 38.66,51.64 38.66,52.12 38.91,52.37 R5.2
_N203: length 4.1
  TOP w0.254: R6.2 38.73,54.53 37.57,53.37 37.57,52.91 37.15,52.49 U1.11
_N204: length 3.7
  TOP w0.254: R7.2 38.86,55.6 37.25,53.99 U1.14
_N213: length 4.4
  TOP w0.254: U1.3 37.55,48.49 37.67,48.62 39.68,48.62 RT.1
_N216: length 3.3
  TOP w0.254: U1.7 38.49,50.49 C4.1
_N217: length 3.5
  TOP w0.254: U1.17 37.87,55.49 39.01,56.64 C5.1
_N227: length 5.3
  TOP w0.254: C6.1 40.05,50.36 39.22,49.53 37.24,49.53 37.2,49.49 U1.5
  TOP w0.381: C6.1 R8.1
_N231: length 5.3
  TOP w0.254: v1(27.95,55.31) 28.54,55.31 28.72,55.49 U1.22
  BOTTOM w0.254: R19.1 27.04,55.34 R18.1 v1(27.95,55.31)
_N232: length 6.3
  TOP w0.254: R16.1 24.04,53.74 C11.1 25,53.78 R15.2 v1(25.48,52.37)
  BOTTOM w0.254: R18.2 27.08,53.09 26.37,52.37 v1(25.48,52.37)
_N233: length 7
  TOP w0.254: U1.21 27.81,55.99 27.45,56.36 25.65,56.36 25.1,55.8 25.1,55.38 R15.1
_N238: length 8.5
  TOP w0.254: C11.2 24.04,54.82 R17.1 24.8,56.82 27.64,56.82 27.96,56.49 U1.20
_N250: length 23.8
  L3_SIG w0.508: v1(18.35,36.25) 17.84,36.75 12.9,36.75 11.76,35.61 v1(11.76,32.46) 11.76,30.94 10.34,29.51 v1(8.43,29.51)
  BOTTOM w0.203: Q5.4 13.1,32.77 Q6.4
  BOTTOM w0.381: v1(11.76,32.46) Q5.4
  BOTTOM w0.508: Q4.1 v1(8.43,29.51) ; C12.2 18.34,38.8 D1.A 18.35,37.21 R20.1 v1(18.35,36.25)
_N274:
  vias: v1(21.26,21.49) v1(21.26,20.47) v1(21.26,19.46) v1(21.26,18.44) v1(21.26,17.42) v1(21.26,16.41) v1(21.26,15.39) v1(21.26,14.38) v1(21.26,13.36) v1(21.26,10.31) v1(21.26,9.3) v1(22.28,21.49) v1(22.28,20.47) v1(22.28,19.46) v1(22.28,18.44) v1(22.28,17.42) v1(22.28,16.41) v1(22.28,15.39) v1(22.28,14.38) v1(22.28,13.36) v1(22.28,10.31) v1(22.28,9.3) v1(23.29,21.49) v1(23.29,20.47) v1(23.29,19.46) v1(23.29,18.44) v1(23.29,17.42) v1(23.29,16.41) v1(23.29,15.39) v1(23.29,14.38) v1(23.29,13.36) v1(23.29,12.34) v1(23.29,11.33) v1(23.29,10.31) v1(23.29,9.3) v1(24.31,21.49) v1(24.31,20.47) v1(24.31,19.46) v1(24.31,18.44) v1(24.31,17.42) v1(24.31,16.41) v1(24.31,15.39) v1(24.31,14.38) v1(25.32,21.49) v1(25.32,20.47) v1(25.32,19.46) v1(25.32,18.44) v1(25.32,17.42) v1(25.32,16.41) v1(25.32,15.39) v1(25.32,14.38) v1(26.34,21.49) v1(26.34,20.47) v1(26.34,19.46) v1(26.34,18.44) v1(26.34,17.42) v1(26.34,16.41) v1(26.34,15.39) v1(26.34,14.38) v1(27.36,21.49) v1(27.36,20.47) v1(27.36,13.36) v1(27.36,12.34) v1(27.36,11.33) v1(27.36,10.31) v1(27.36,9.3) v1(27.53,19.48) v1(27.53,17.96) v1(27.53,16.43) v1(27.53,14.91) v1(28.37,21.49) v1(28.37,20.47) v1(29.05,19.48) v1(29.05,17.96) v1(29.05,16.43) v1(29.05,14.91) v1(29.39,21.49) v1(29.39,20.47) v1(30.4,21.49) v1(30.4,20.47) v1(30.58,19.48) v1(30.58,17.96) v1(30.58,16.43) v1(30.58,14.91) v1(31.42,21.49) v1(31.42,20.47) v1(32.1,19.48) v1(32.1,17.96) v1(32.1,16.43) v1(32.1,14.91) v1(32.44,21.49) v1(32.44,20.47) v1(33.45,21.49) v1(33.45,20.47) v1(33.45,19.46) v1(33.45,18.44) v1(33.45,17.42) v1(34.47,21.49) v1(34.47,20.47) v1(34.47,19.46) v1(34.47,18.44) v1(34.47,17.42) v1(35.48,21.49) v1(35.48,20.47) v1(35.48,18.44) v1(35.48,17.42) v1(36.5,21.49) v1(36.5,20.47) v1(36.5,18.44) v1(36.5,17.42) v1(37.52,21.49) v1(37.52,20.47) v1(37.52,18.44) v1(37.52,17.42) v1(38.53,21.49) v1(38.53,20.47) v1(38.53,19.46) v1(38.53,18.44) v1(38.53,17.42) v1(39.55,21.49) v1(39.55,20.47) v1(39.55,19.46) v1(39.55,18.44) v1(39.55,17.42) v1(40.56,21.49) v1(40.56,20.47) v1(40.56,19.46) v1(40.56,18.44) v1(40.56,17.42) v1(41.58,21.49) v1(41.58,20.47) v1(41.58,19.46) v1(41.58,18.44) v1(42.6,21.49) v1(42.6,20.47) v1(42.6,19.46) v1(42.6,18.44) v1(42.65,2.89) v1(44.68,2.89) v1(46.2,2.89) v1(48.23,2.89) v1(59.41,20.12) v1(59.41,15.04) v1(59.41,9.96)
_N303: length 12.9
  TOP w0.254: C6.2 39.92,49.07 37.44,49.07 37.36,48.99 U1.4
  TOP w0.381: v1(42.62,49.33) 42.59,49.36 R8.2 C6.2
  BOTTOM w0.508: v1(42.62,49.33) 43.36,48.59 R9.1
_N305: length 3.2
  BOTTOM w0.508: 51.05,48.59 R10.1 ; 51.05,48.59 R9.2 ; 51.05,48.59 52.98,48.59 U3.3
_N365:
  vias: v1(2.97,34.19) v1(2.97,31.65) v1(2.97,29.11) v1(5.51,32.92) v1(5.51,30.38) v1(10.59,27.84) v1(10.59,25.3) v1(13.13,26.57) v1(15.16,28.09) v1(15.16,27.08) v1(15.16,26.06) v1(16.18,34.19) v1(16.18,32.16) v1(16.18,30.12) v1(16.18,28.09) v1(16.18,27.08) v1(16.18,26.06) v1(17.2,28.09) v1(17.2,27.08) v1(17.2,26.06) v1(18.21,34.19) v1(18.21,32.16) v1(18.21,30.12) v1(18.21,28.09) v1(18.21,27.08) v1(18.21,26.06) v1(19.23,28.09) v1(19.23,27.08) v1(19.23,26.06) v1(20.24,34.19) v1(20.24,32.16) v1(20.24,30.12) v1(20.24,28.09) v1(20.24,27.08) v1(20.24,26.06) v1(21.26,34.19) v1(21.26,33.17) v1(21.26,32.16) v1(21.26,31.14) v1(21.26,30.12) v1(21.26,29.11) v1(21.26,28.09) v1(21.26,27.08) v1(21.26,26.06) v1(22.28,34.19) v1(22.28,33.17) v1(22.28,32.16) v1(22.28,31.14) v1(22.28,30.12) v1(22.28,29.11) v1(22.28,28.09) v1(22.28,27.08) v1(22.28,26.06) v1(23.29,34.19) v1(23.29,33.17) v1(23.29,32.16) v1(23.29,31.14) v1(23.29,30.12) v1(23.29,29.11) v1(23.29,28.09) v1(23.29,27.08) v1(23.29,26.06) v1(24.31,34.19) v1(24.31,33.17) v1(24.31,32.16) v1(24.31,31.14) v1(24.31,30.12) v1(24.31,29.11) v1(24.31,28.09) v1(24.31,27.08) v1(24.31,26.06) v1(25.32,34.19) v1(25.32,33.17) v1(25.32,32.16) v1(25.32,31.14) v1(25.32,30.12) v1(25.32,29.11) v1(25.32,28.09) v1(25.32,27.08) v1(25.32,26.06) v1(26.34,34.19) v1(26.34,33.17) v1(26.34,32.16) v1(26.34,31.14) v1(26.34,30.12) v1(26.34,29.11) v1(26.34,28.09) v1(26.34,27.08) v1(26.34,26.06) v1(27.36,34.19) v1(27.36,33.17) v1(27.36,32.16) v1(27.36,31.14) v1(27.36,30.12) v1(27.36,29.11) v1(27.36,28.09) v1(27.36,27.08) v1(27.36,26.06) v1(28.37,34.19) v1(28.37,33.17) v1(28.37,32.16) v1(28.37,31.14) v1(28.37,30.12) v1(28.37,29.11) v1(28.37,28.09) v1(28.37,27.08) v1(28.37,26.06) v1(29.39,32.16) v1(29.39,31.14) v1(29.39,30.12) v1(29.39,29.11) v1(29.39,28.09) v1(29.39,27.08) v1(29.39,26.06) v1(30.4,30.12) v1(30.4,29.11) v1(30.4,28.09) v1(30.4,27.08) v1(30.4,26.06) v1(31.42,30.12) v1(31.42,29.11) v1(31.42,28.09) v1(31.42,27.08) v1(31.42,26.06) v1(32.44,30.12) v1(32.44,29.11) v1(32.44,28.09) v1(32.44,27.08) v1(32.44,26.06) v1(33.45,30.12) v1(33.45,29.11) v1(33.45,28.09) v1(33.45,27.08) v1(33.45,26.06) v1(34.47,30.12) v1(34.47,29.11) v1(34.47,28.09) v1(34.47,27.08) v1(34.47,26.06) v1(37.52,33.93) v1(37.52,30.89) v1(39.55,32.92)
_N372: length 2.3
  TOP w0.381: v1(29.6,54.85) 29.96,54.49 U1.24
  BOTTOM w0.381: v1(29.6,54.85) 29.29,55.16 R23.1
INTVCC: length 26.3
  TOP w0.381: U1.26 v1(29.59,53.49)
  BOTTOM w0.508: v1(29.59,53.49) 30.14,53.49 30.73,54.09 C3.1 31.2,54.09 32.26,55.14 40.03,55.14 42.14,53.04 50.37,53.04 50.94,52.46 R11.1
N396:
  vias: v1(1.7,36.47) v1(2.97,36.47) v1(8.96,44.93) v1(8.96,42.39) v1(20.24,45.11) v1(20.24,43.08) v1(20.24,40.03) v1(20.24,39.01) v1(20.24,35.97) v1(21.26,40.03) v1(21.26,39.01) v1(22.28,45.11) v1(22.28,43.08) v1(22.28,40.03) v1(22.28,39.01) v1(23.29,40.03) v1(23.29,39.01) v1(23.29,35.97) v1(24.31,45.11) v1(24.31,43.08) v1(24.31,40.03) v1(24.31,39.01) v1(24.31,38) v1(24.31,36.98) v1(24.31,35.97) v1(25.32,45.11) v1(25.32,44.09) v1(25.32,43.08) v1(25.32,42.06) v1(25.32,41.05) v1(25.32,40.03) v1(25.32,39.01) v1(25.32,38) v1(25.32,36.98) v1(25.32,35.97) v1(26.34,45.11) v1(26.34,43.08) v1(26.34,40.03) v1(26.34,39.01) v1(26.34,38) v1(26.34,36.98) v1(26.34,35.97) v1(27.36,40.03) v1(27.36,39.01) v1(27.36,38) v1(27.36,36.98) v1(27.36,35.97) v1(28.37,45.11) v1(28.37,43.08) v1(28.37,40.03) v1(28.37,39.01) v1(28.37,38) v1(28.37,36.98) v1(28.37,35.97) v1(29.39,40.03) v1(29.39,39.01) v1(29.39,38) v1(29.39,36.98) v1(30.4,45.11) v1(30.4,43.08) v1(30.4,40.03) v1(30.4,39.01) v1(30.4,38) v1(30.4,36.98) v1(31.42,45.11) v1(31.42,44.09) v1(31.42,43.08) v1(31.42,42.06) v1(31.42,41.05) v1(31.42,40.03) v1(31.42,39.01) v1(31.42,38) v1(31.42,36.98) v1(32.44,45.11) v1(32.44,44.09) v1(32.44,43.08) v1(32.44,42.06) v1(32.44,41.05) v1(32.44,40.03) v1(32.44,39.01) v1(32.44,38) v1(32.44,36.98) v1(33.45,45.11) v1(33.45,44.09) v1(33.45,43.08) v1(33.45,42.06) v1(33.45,41.05) v1(33.45,40.03) v1(33.45,39.01) v1(33.45,38) v1(33.45,36.98) v1(34.47,45.11) v1(34.47,44.09) v1(34.47,43.08) v1(34.47,42.06) v1(34.47,41.05) v1(34.47,40.03) v1(34.47,39.01) v1(34.47,38) v1(34.47,36.98) v1(34.47,35.97) v1(35.48,45.11) v1(35.48,44.09) v1(35.48,43.08) v1(35.48,42.06) v1(35.48,41.05) v1(35.48,40.03) v1(35.48,39.01) v1(35.48,38) v1(35.48,36.98) v1(35.48,35.97) v1(36.5,45.11) v1(36.5,44.09) v1(36.5,43.08) v1(36.5,42.06) v1(36.5,41.05) v1(36.5,40.03) v1(36.5,39.01) v1(36.5,38) v1(36.5,36.98) v1(36.5,35.97) v1(37.52,45.11) v1(37.52,44.09) v1(37.52,43.08) v1(37.52,42.06) v1(37.52,41.05) v1(37.52,40.03) v1(37.52,39.01) v1(37.52,38) v1(37.52,36.98) v1(37.52,35.97) v1(38.53,45.11) v1(38.53,44.09) v1(38.53,43.08) v1(38.53,42.06) v1(38.53,41.05) v1(38.53,40.03) v1(38.53,39.01) v1(38.53,38) v1(38.53,36.98) v1(38.53,35.97)
N430: length 22.8
  TOP w0.254: R24.2 27.64,53.91 v1(28.03,53.52)
  L3_SIG w0.508: v1(25.02,48.29) 28.91,48.29 v1(29.72,49.1) 30.48,49.1 31.39,50.01 31.39,54.97 30.68,55.68 29.29,55.68 28.78,55.17 28.78,54.03 28.27,53.52 v1(28.03,53.52)
  BOTTOM w0.381: R23.2 28.78,54.03 28.27,53.52 v1(28.03,53.52)
  BOTTOM w0.508: Q2.4 24.18,47.9 24.56,48.29 v1(25.02,48.29) ; Q1.4 30.2,48.62 v1(29.72,49.1)
N436: length 0.9
  TOP w0.508: R16.2 v1(21.49,52.45)
SYNC: length 18.1
  TOP w0.254: v1(39.24,50.39) 38.84,49.99 U1.6
  L3_SIG w0.508: v1(43.08,51.03) 46.69,51.03 SYNC.1
  BOTTOM w0.508: v1(39.24,50.39) 39.28,50.36 RSYNC.1 41.04,50.36 41.71,51.03 v1(43.08,51.03)
VFB: length 42
  BOTTOM w0.508: R14.2 53.18,35.92 U2.2 50.88,35.92 50.16,35.2 RFB2.1 RFB1.2 C13.2 51.16,30.57 56.79,24.94 56.79,6.48 TRIM.1
VO: length 35.2
  TOP w0.508: v1(58.32,12.95) v1(58.32,12.19)
  TOP w1.016: 37.41,2.21 UNK+VOUT.1 ; UNK+VOUT.1 39.7,2.21 ; UNK+VOUT.1 38.56,3.35
  L2_GND w0.508: v1(58.32,12.95) v1(58.32,12.19)
  L6_PWR w0.508: v1(58.32,12.95) v1(58.32,12.19)
  L7_GND w0.508: v1(58.32,12.95) v1(58.32,12.19)
  BOTTOM w0.508: RFB1.1 C13.1 52.16,31.81 52.98,30.99 R13.1 54.86,29.04 58.32,25.58 v1(58.32,12.95) v1(58.32,12.19)
  BOTTOM w1.016: 37.41,2.21 UNK+VOUT.1 ; UNK+VOUT.1 38.56,3.35 ; UNK+VOUT.1 39.7,2.21
  vias: v1(35.53,4.92) v1(35.53,3.9) v1(35.53,2.89) v1(35.53,1.87) v1(36.55,4.92) v1(36.55,3.9) v1(36.55,2.89) v1(36.55,1.87) v1(37.57,4.92) v1(37.57,3.9) v1(39.09,4.92) v1(39.09,3.9) v1(40.11,4.92) v1(40.11,3.9) v1(40.11,2.89) v1(40.11,1.87) v1(41.12,4.92) v1(41.12,3.9) v1(41.12,2.89) v1(41.12,1.87) v1(42.65,4.92) v1(42.65,3.9) v1(43.66,4.92) v1(43.66,3.9) v1(44.68,4.92) v1(44.68,3.9) v1(46.2,4.92) v1(46.2,3.9) v1(47.22,4.92) v1(47.22,3.9) v1(48.23,4.92) v1(48.23,3.9) v1(52.13,12.83) v1(52.13,11.81) v1(52.13,10.79) v1(53.15,12.83) v1(53.15,11.81) v1(53.15,10.79) v1(54.16,12.83) v1(54.16,11.81) v1(54.16,10.79) v1(55.18,12.83) v1(55.18,11.81) v1(55.18,10.79)

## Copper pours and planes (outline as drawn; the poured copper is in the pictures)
AGND on TOP: 1.02,57.4 59.94,57.4 59.94,46.46 40,46.46 40,24.87 1.02,24.87 ; 1 cut-out
AGND on BOTTOM, L2_GND, L3_SIG, L6_PWR, L7_GND: 1.02,57.4 59.94,57.4 59.94,46.46 40,46.46 40,24.87 1.02,24.87
AGND on L4_PWR, L5_PWR: 1.02,57.4 59.94,57.4 59.94,46.46 1.02,46.46
GND_ISO on TOP, L2_GND, L3_SIG, L6_PWR, L7_GND: 42.04,44.42 59.94,44.42 59.94,1.02 1.02,1.02 1.02,22.83 42.04,22.83
GND_ISO on BOTTOM: 42.04,44.42 59.94,44.42 59.94,1.02 1.02,1.02 1.02,22.83 42.04,22.83 ; 4 cut-outs
GND_ISO on L4_PWR, L5_PWR: 42.04,44.42 59.94,44.42 59.94,24.88 42.04,24.88
VIN on TOP: 1.04,57.4 12.83,57.4 12.83,39.98 10.03,39.98 6.82,43.19 1.04,43.19
VIN on BOTTOM: 2.34,57.4 11.79,57.4 12.83,57.4 12.83,39.98 1.02,39.98 1.02,56.08
VIN on L3_SIG: 11.13,53.52 9.86,53.52 9.6,53.26 9.6,50.98 9.86,50.72 11.13,50.72 11.38,50.98 11.38,53.26
VIN on L3_SIG: 11.13,49.96 9.86,49.96 9.6,49.71 9.6,47.42 9.86,47.17 11.13,47.17 11.38,47.42 11.38,49.71
VIN on L3_SIG: 11.13,42.85 9.86,42.85 9.6,42.6 9.6,40.31 9.86,40.06 11.13,40.06 11.38,40.31 11.38,42.6
VIN on L3_SIG: 11.13,46.41 9.86,46.41 9.6,46.15 9.6,43.87 9.86,43.61 11.13,43.61 11.38,43.87 11.38,46.15
VIN on L3_SIG: 6.36,57.4 10.26,57.4 11.96,57.4 11.96,54.28 6.36,54.28
VIN_X on TOP: 1.02,40.99 8.06,40.99 10.02,39.03 10.02,36.96 9.25,36.18 1.02,36.18
_N37 on TOP, L3_SIG, L6_PWR: 15.8,18.2 15.8,1.02 1.02,1.02 1.02,18.2
_N37 on BOTTOM: 11.52,1.02 2.62,1.02 1.02,2.62 1.02,18.2 19.35,18.2 19.35,11.75 14.51,11.75 14.51,6.65 11.52,6.65
_N37 on L4_PWR, L5_PWR: 1.02,22.83 19.35,22.83 19.35,1.02 1.02,1.02
_N264 on BOTTOM: 48.97,18.92 55.52,18.92 55.52,22.83 48.97,22.83
_N265 on BOTTOM: 43.79,16.56 43.79,22.83 47.55,22.83 47.55,16.56
_N274 on TOP: 43.26,21.77 43.26,14.27 31.06,14.27 31.06,9.19 30.66,8.79 20.73,8.79 20.73,21.77
_N274 on BOTTOM, L3_SIG, L6_PWR: 42.88,21.77 42.88,16.56 32.97,16.56 32.97,14.32 27.89,14.32 27.89,8.79 20.73,8.79 20.73,21.77
_N274 on L4_PWR, L5_PWR: 20.73,22.83 59.94,22.83 59.94,1.02 20.73,1.02
_N310 on BOTTOM: 31.65,34.72 31.65,31.52 40,31.52 40,34.72
_N365 on TOP, BOTTOM, L3_SIG, L6_PWR: 14.53,25.84 14.53,34.72 31.09,34.72 31.09,31.01 34.72,31.01 34.72,25.84
_N365 on L4_PWR, L5_PWR: 1.02,34.72 40,34.72 40,24.87 1.02,24.87
_N375 on BOTTOM: 33.82,11.33 29.66,11.33 29.66,13.13 33.82,13.13
_N387 on BOTTOM: 17.56,2.58 13.41,2.58 13.41,4.38 17.56,4.38
N396 on TOP, BOTTOM, L3_SIG, L6_PWR: 20.04,45.95 20.04,35.26 40,35.26 40,45.95
N396 on L4_PWR, L5_PWR: 1.02,45.95 40,45.95 40,35.26 1.02,35.26
N436 on BOTTOM: 20.07,46.75 29.24,46.75 29.24,51.16 27.64,52.76 20.07,52.76
VO on TOP: 49.2,17.14 55.52,17.14 55.52,7.52 49.02,1.02 35.08,1.02 35.08,7.29 35.48,7.7 48.79,7.7 49.2,8.1
VO on BOTTOM: 49.2,17.14 55.52,17.14 55.52,7.52 49.02,1.02 35.08,1.02 35.08,7.29 48.72,7.29 49.2,7.77
VO on L3_SIG: 51.79,13.23 51.79,10.39 55.52,10.39 55.52,11.91 58.62,11.91 58.62,13.23
VO on L3_SIG, L6_PWR: 41.22,3.61 38.94,3.61 38.68,3.86 38.68,5.13 38.94,5.38 41.22,5.38 41.48,5.13 41.48,3.86
VO on L3_SIG, L6_PWR: 48.34,3.61 46.05,3.61 45.8,3.86 45.8,5.13 46.05,5.38 48.34,5.38 48.59,5.13 48.59,3.86
VO on L3_SIG, L6_PWR: 37.95,4.85 37.95,3.58 38.3,3.23 41.35,3.23 41.61,2.97 41.61,1.02 35.15,1.02 35.15,4.9 35.51,5.26 37.54,5.26
VO on L3_SIG, L6_PWR: 44.78,3.61 42.49,3.61 42.24,3.86 42.24,5.13 42.49,5.38 44.78,5.38 45.03,5.13 45.03,3.86
VO on L6_PWR: 51.79,13.23 51.79,10.39 55.52,10.39 55.52,13.23

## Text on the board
Ref Des/Silkscreen Bottom: C | SECONDARY SIDE | 08-084066 REV B Z
User.Comments: 4.    INSTALL M027930 AND M028071 ON 4 PLACES. | 4.    SEE CNMILLMAX3310X_ASSY_DETAIL FOR THE ASSEMBLY FOR THE FOLLOWING REFDES: | +VIN, +VOUT, -VIN, -VOUT, RC, SYNC, TRIM
Ref Des/Silkscreen Top: 08-084066 REV B Z | PRIMARY SIDE | AD-PSXXXX-RD
PAGE_OUTLINE: TEST PROCESS | N/A
BODY_CENTER: FAB NOTES REVISION: NOVEMBER 21 2022 | 8.   IMPEDANCE REQUIREMENTS: IF NO STACKUP IS DEFINED, THE VENDOR IS ALLOWED TO ADJUST THE DIELECTRIC | 13.  PLATING SPECIFICATION: | 1.   DIMENSIONS ARE IN INCHES (EXCEPT WHERE NOTED). | ALL DOCUMENTS & SPECIFICATIONS REFERRED TO BELOW SHOULD BE THE LATEST REVISIONS. | 2.  BOARD MATERIAL:(USE CHECKED ITEMS) | 3.   ALL LAMINATES & BONDING MATERIALS SHOULD BE SELECTED FROM IPC-4101 OR IPC-4103,(TG>170 DEGC TD>300 DEGC) | 4.   REFER TO IPC-6010 SERIES, CLASS 2 FOR FABRICATION. | 5.   REFER TO LAMINATION DIAGRAM FOR OVERALL BOARD THICKNESS, TOLERANCE APPLIES AFTER ALL LAMINATION AND PLATING | 6.   BOW & TWIST NOT TO EXCEED 0.0075 INCHES (0.75%) PER LINEAR INCH AND SHOULD BE MEASURED PER IPC-TM-650, METHOD 2.4.22. | 7.   ACCEPTABILITY PER ADI SPECIFICATION TST00115. | 9.   FILLET OPTIONS TO ENHANCE RELIABILITY AT PAD JUNCTIONS WHERE SPACING PERMITS. | 10.  THIEVING: | 11.  LAYER TO LAYER REGISTRATION SHALL BE WITHIN 0.003 INCHES. | 12.  DRILL SIZES ARE FINISHED HOLE SIZES. ALL HOLES SHALL BE LOCATED WITHIN 0.005 INCHES DTP,UNLESS SPECIFIED. | 14.  SURFACE FINISH: | 15.  SOLDERMASK: | 16.  APPLY SILKSCREEN TO BOTH SIDES USING A NON-CONDUCTIVE, EPOXY BASED INK PER ARTWORK. | (X) WHITE | ( ) OTHER | PROCESSES. FINISHED THICKNESS MEASURED FROM TOP COPPER TO BOTTOM COPPER. | (X)  ISOLA 370HR OR S1000-2 OR IT180 OR EQUIVALENT | ( )  ISOLA-FR408HR OR EQUIVALENT | ( )  ISOLA IS410 | ( )  MEGTRON 6 | ( )  NELCO-4000-13 | ( )  ROGERS 4350B | ( ) ROGERS 3003 | ( ) ARLON 85N | ( ) EM370D | ( )  OTHER ________________________ | ( ) FILLETS ALLOWED | (X) FILLETS NOT ALLOWED | ( ) VENDOR MAY ADD THIEVING TO COMPENSATE FOR LOW COPPER DENSITY AREAS MAINTAINING A MINIMUM | ( ) VENDOR MAY NOT ADD THIEVING TO COMPENSATE FOR LOW COPPER DENSITY AREAS. | (X) LPI | ( ) OTHER_________ | COLOR | (X) GREEN | HINDER PROPER SOLDER WICKING. BARREL RELIEF ON SOLDERMASK ALLOWED IN UNFILLED VIA IN PAD HOLES. | (X) REFER TO LAMINATION DIAGRAM FOR FINISHED COPPER WEIGHT/THICKNESS REQUIRMENTS | (X) IMMERSION GOLD (ENIG) 1.58-3.94 MICRO INCHES OVER 118-236 MICRO INCHES MIN. OF ELECTROLESS NICKEL PER IPC-4552 | ( ) OSP (ORGANIC SOLDERABILITY PRESERVATIVE) | ( ) IMMERSION SILVER | ( ) SOFT WIRE BONDABLE GOLD 30-50 MICRO INCHES OF SOFT WIRE | ( ) EDGE CONNECTOR FINGERS ARE TO BE PLATED WITH 100 MICRO-INCHES(.0001") OF LOW STRESS | THICKNESS & TRACE WIDTHS TO MEET THE IMPEDANCE REQUIREMENT. IF SPECIFIED, THE VENDOR MUST | TRACE WIDTH & SPACING THAT IMPACT THE REQUIREMENTS MUST HAVE WRITTEN APPROVAL FROM ADI. | MINIMUM BARREL PLATING OF 0.001 INCHES. PLATED HOLES SHALL NOT BE ROUGH OR IRREGULAR SO AS TO | SOLDERMASK OVER BARE COPPER OR BARE GOLD (BOTH SIDES) TO MEET IPC-SM-840. | IF PRESENT,DO NOT MODIFY SOLDERMASK DEFINED PADS (MASK OPENINGS LESS THAN COPPER PAD) WITHOUT APPROVAL. | MEET THE REQUIREMENTS LISTED IN THE IMPEDANCE TABLE. ANY ADJUSTMENT MADE TO THE DEFINED STACKUP, | UL FLAMMABILITY RATING 94V-0. BOARD MATERIAL & CONSTRUCTION SHALL MEET THE REQUIREMENTS OF UL796/UL796F. | BONDABLE GOLD OVER 100-150 MICRO INCHES OF NICKEL | NICKEL UNDER 30 MICRO-INCHES (.00003') OF GOLD | 0.100 INCH CLEARANCE FROM ALL COPPER FEATURES, | THE STARTING COPPER WEIGHT/THICKNESS CAN VARY AS LONG AS THE FINISHED COPPER | WEIGHT/THICKNESS IS NOT LESS THAN THE SPECIFIED VALUE. | UNLESS OTHERWISE SPECIFIED | HOMOGENOUS MATERIALS IN THIS BOARD SHALL BE COMPLAINT WITH THE EU DIRECTIVE 2002/95/EC | WORKMANSHIP SHALL CONFORM TO IPC-A-600, CLASS 2. | 21.  INTENTIONAL SHORTS: | 17.  FINAL ELECTRICAL TEST TO BE PERFORMED USING PROVIDED IPC-D-356A NETLIST OR ODB++ FORMAT FILE. | 22.  PEMNUTS: | 23.  MANUFACTURER TO ETCH/STAMP WITH PERMANENT NON-CONDUCTIVE INK | ON SECONDARY SIDE UNLESS OTHERWISE SPECIFIED: | 18.  A TIME DOMAIN REFLECTOMETER REPORT (TDR) FOR EACH IMPEDANCE CONTROLLED LAYER & A CERTIFICATE | 19.  IF PRESENT, ALL BLIND/BURIED VIAS WITH AN ASPECT RATIO <1:1 TO BE PLATED SHUT WITH COPPER WHEN | 20.  FOR VIA FILL INFORMATION REFER TO DRILL CHART: | 24.  MINIMUM DESIGN LINE WIDTH IS .010 INCH. | 25.  MINIMUM DESIGN LINE SPACING IS .008 INCH. | 25. BOARDS TO BE SHIPPED SINGULATED AFTER FABRICATION PROCESS | IS ACCEPTABLE, ALL OTHER INSTANCES MUST BE REPORTED. | IF AN INTENTIONAL SHORT REPORT IS SUPPLIED AND DOES NOT MATCH THE FAB DATA THEN | THE PCB SHALL HAVE A VERIFICATION STAMP. | ( )  NON-CONDUCTIVE EPOXY FILL ALL 0.XXXX INCHES DRILLED VIAS | ( )  COPPER FILL ALL 0.XXXX INCHES DRILLED VIAS | ( ) PEMNUTS TO BE INSTALLED BY FABRICATOR | ( ) PEMNUTS NOT TO BE INSTALLED BY FABRICATOR | ( ) NOT APPLICABLE | USED AS VIA-IN-PAD OR AS A STACKED VIA. BLIND/BURIED VIAS WITH AN ASPECT RATIO >1:1 TO BE FILLED | A. UL CODE-FLAMMABILITY RATING FOR THOSE APPROVED MATERIALS(IF APPLICABLE) | B. DATE CODE | C. LOT NUMBER | D. MANUFACTURER LOGO | SMOOTHEN EDGES AND FREE FROM BURRS AFTER DEPANELIZATION PROCESS | CAN'T BE PERFORMED BECAUSE THE TRACE LENGTH IS TOO SHORT ON THE OUTER LAYERS AT THE PIN ESCAPES | ADI APPROVAL IS REQUIRED. | OF COMPLIANCE SHALL BE PROVIDED BY VENDOR AT TIME OF SHIPMENT. INSTANCES WHERE TDR TESTING | WITH NON-CONDUCTIVE EPOXY. | NOTES: | TOOLING: | FINISH: | MATERIAL: | TESTING: | MISCELLANEOUS:
DIMENSION: LABEL PLACEMENT INFORMATION | HALF SIZE LABELS ARE | AVAILABLE IN THE LIBRARY | PLACE WHEELIE BIN LOGO | TO SUIT THE LAYOUT. | PLACE ROHS COMPLIANT LOGO | TO SUIT THE LAYOUT OR | DELETE IF NOT REQ'D. | PLACE CHINA ROHS COMPLIANT | LOGO TO SUIT THE LAYOUT OR | 1.THE BOARD SIZE CAN BE ADJUSTED TO SUIT THE APPLICATION. | 2.THE MOUNTING HOLES CAN BE MOVED/REMOVED TO SUIT THE APPLICATION. | 3.THE FIDUCIALS CAN BE MOVED TO SUIT THE APPLICATION. | 4.ADJUST THE DIMENSIONS TO SUIT THE APPLICATION. | 5.ADD THE CORRECT LAYER STACKUP ON FAB2 BASED ON THE NO OF LAYERS ON THE PCB. | 6.THE ROHS COMPLIANT AND WHEELIE BIN LOGO'S CAN BE MOVED TO THE DESIRED LOCATION. | HALF SIZE VERSIONS OF THE LABELS ARE AVAILABLE IN THE LIBRARY. | NOTES FOR TEMPLATE USAGE. | REF | DIA MAX | GENERIC D-SIZE TEMPLATE BR-067706A
User.11: SEE ASSY NOTES#4 | SEE ASSY NOTES#5
User.12: ASSEMBLY NOTES (SECONDARY SIDE) | 1.    Q4 (DMP10H400SK3-13), Q5 (SISS71DN-T1-GE3) AND Q6 (SIR873DP-T1-GE3) | IS PLACED OVERLAP FOR EXPERIMENTAL PURPOSES. | CHECK THE BOM ON WHAT PART NUMBER WILL BE INSTALLED. | CLOSELY CHECK FOR SHORTS AND SOLDER BRIDGING.
User.22: L2 GND | 08-      -07
User.23: L3 SIG | 08-      -08
User.24: 08-      -09 | L4 SIG
User.25: 08-      -10 | L5 PWR
User.27: L6 PWR | 08-      -11
User.28: L7 GND | 08-      -12
User.45: FIGURE | SIZE | 10.0 | 50.0 | 125.0 | DRILL CHART: TOP to BOTTOM | FINISHED HOLES IN MILS | PLATED | NON-PLATED | QTY | 1065 | 7 | 4 | 1076 | TOLERANCE/NOTES | TOTAL HOLES:
